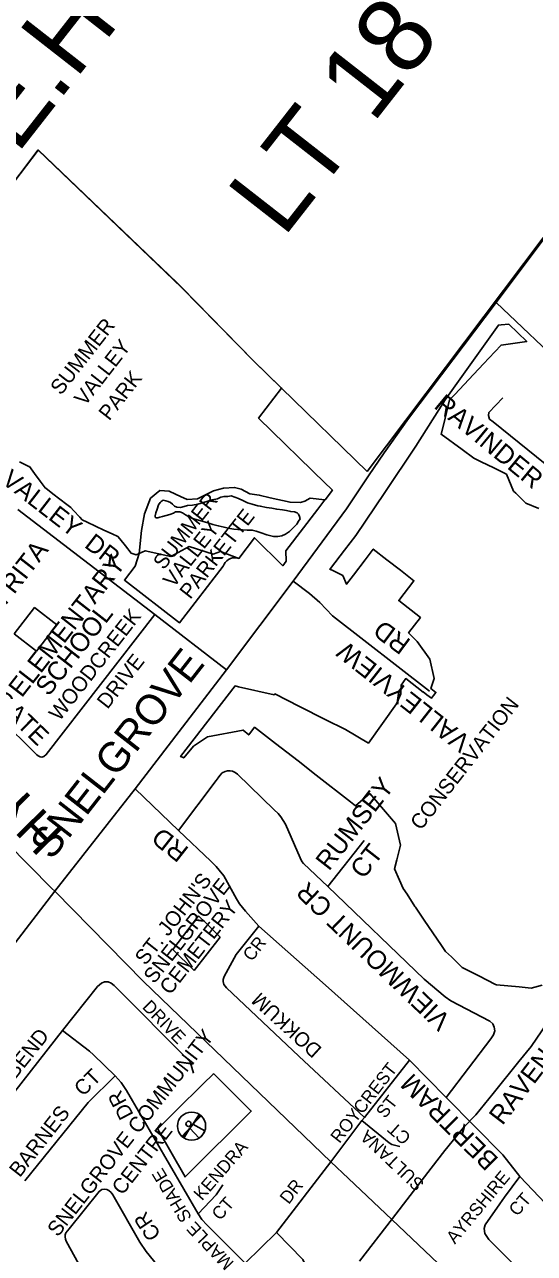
# Model space of a CAD drawing. Extents: x 586326 to 623965, y 4819854 to 4857850.
# Drawn here: x 594587 to 595265, y 4842493 to 4844128 of the extents above; entities that cross this region are included whole.
import ezdxf

# ---------------------------------------------------------------- set-up
doc = ezdxf.new("R2010")
doc.units = 0
for name, color, linetype in [('Cemeteries', 7, 'Continuous'), ('Lots_Concessions', 7, 'Continuous'), ('Major Rds and Hwys', 7, 'Continuous'), ('Major Rds Lbls', 7, 'Continuous'), ('Minor Rd Lbls', 7, 'Continuous'), ('Minor Rds', 7, 'Continuous'), ('Municipal Bdry', 7, 'Continuous'), ('Park Lbls', 7, 'Continuous'), ('Park Outlines', 7, 'Continuous'), ('Proposed Secondary Rds', 7, 'Continuous'), ('Pts of Interest', 7, 'Continuous'), ('Rec Lbls', 7, 'Continuous'), ('Rec Syms', 7, 'Continuous'), ('School Syms_Lbls', 7, 'Continuous'), ('Secondary Rds Lbls', 7, 'Continuous'), ('SWM Ponds', 7, 'Continuous')]:
    doc.layers.add(name, color=color, linetype=linetype)

msp = doc.modelspace()

# ---------------------------------------------------------------- linework, layer by layer
at = {"layer": 'Cemeteries'}
for p, q in [((594818.1, 4842941.8), (594783.8, 4842897.1)), ((594827.7, 4842932.3), (594818.1, 4842941.8)), ((594844.9, 4842915.3), (594827.7, 4842932.3)), ((594812.3, 4842868.8), (594846.8, 4842913.5)), ((594846.8, 4842913.5), (594844.9, 4842915.3)), ((594783.8, 4842897.1), (594812.3, 4842868.8))]:
    msp.add_line(p, q, dxfattribs=at)
at = {"layer": 'Lots_Concessions'}
for p, q in [((595260.4, 4842768), (595323.9, 4842861.7)), ((595244, 4842747.7), (595260.4, 4842768)), ((595210, 4842705.5), (595244, 4842747.7)), ((595186.9, 4842677), (595210, 4842705.5)), ((595170.7, 4842660.7), (595186.9, 4842677)), ((595145.8, 4842629.4), (595170.7, 4842660.7)), ((595127.6, 4842606.1), (595145.8, 4842629.4)), ((595075.9, 4842539.1), (595127.6, 4842606.1)), ((595032.3, 4842482), (595075.9, 4842539.1))]:
    msp.add_line(p, q, dxfattribs=at)
at = {"layer": 'Major Rds and Hwys'}
for points in [[(595213.8, 4843758), (595457.2, 4844082.7)], [(594944.1, 4843386.9), (595015, 4843483.4), (595044.2, 4843527.2), (595064.9, 4843558.1), (595097.4, 4843603.4), (595213.8, 4843758)], [(594626.9, 4842974.4), (594623.1, 4842978.3), (594563.3, 4843039), (594441.7, 4843162.2), (594366, 4843239), (594228, 4843378.9)], [(594855.4, 4843269.1), (594944.1, 4843386.9)], [(594733.6, 4843110.7), (594855.4, 4843269.1)], [(594626.9, 4842974.4), (594733.6, 4843110.7)], [(594341.1, 4842602.5), (594626.9, 4842974.4)], [(594994, 4842614.6), (594744.9, 4842854.2), (594626.9, 4842974.4)], [(595260.2, 4842361.6), (595075, 4842537.6), (595017.6, 4842592.1), (594994, 4842614.6)]]:
    msp.add_lwpolyline(points, dxfattribs=at)
at = {"layer": 'Minor Rds'}
for points in [[(595213.8, 4843758), (595310, 4843666.5), (595318.1, 4843656.8), (595324.3, 4843648.5), (595329.5, 4843640.5), (595334.4, 4843631.5), (595339.1, 4843620.7), (595343.1, 4843609), (595346.2, 4843598.1), (595348.5, 4843586.2), (595355.8, 4843529.1)], [(595355.8, 4843529.1), (595320.1, 4843525.3), (595312.7, 4843525.2), (595304, 4843527.1), (595297.4, 4843529.9), (595290.7, 4843533.8), (595209.7, 4843599.3), (595205.2, 4843602.7), (595203.5, 4843607.5), (595204.2, 4843611.5), (595222.9, 4843631)], [(594759.9, 4843342.7), (594577.9, 4843482.6)], [(594944.1, 4843386.9), (594965.6, 4843370.7), (594979.3, 4843358.9), (594996.3, 4843341.1), (595125.4, 4843240.8)], [(594759.9, 4843342.7), (594615.5, 4843156.3), (594612.4, 4843153.7), (594609.7, 4843152.9), (594607.4, 4843153.2), (594604.9, 4843154.5), (594602.8, 4843156.2)], [(594855.4, 4843269.1), (594759.9, 4843342.7)], [(594602.8, 4843156.2), (594552.4, 4843205.6)], [(594955.6, 4843014.2), (594953.1, 4843018.9), (594933.7, 4843063.6), (594930.7, 4843068.8), (594927.6, 4843073.3), (594923.8, 4843077.8), (594918.8, 4843082.8), (594869.7, 4843130.4), (594866.7, 4843132.5), (594863.2, 4843134.1), (594860.1, 4843134.8), (594856.6, 4843134.7), (594853.4, 4843133.8), (594849.6, 4843131.9), (594846.6, 4843128.6), (594844, 4843125.2), (594841.3, 4843121.7), (594791.4, 4843055.5)], [(594989.9, 4842980.9), (595038.5, 4843042.1)], [(594989.9, 4842980.9), (594957.6, 4843011.5), (594955.6, 4843014.2)], [(595147.4, 4842700.2), (595207, 4842778.1), (595210.4, 4842783.4), (595212.3, 4842788.6), (595211.4, 4842793.4), (595209.4, 4842798.2), (595205.5, 4842801.7), (595153.7, 4842828.5), (595146.1, 4842834.1), (595118.2, 4842857.3), (594989.9, 4842980.9)], [(594898.4, 4842928), (594868.1, 4842890.2), (594852.2, 4842861.1), (594851, 4842857.1), (594850.9, 4842854.2), (594851.9, 4842850.5), (594855.2, 4842846), (594951.3, 4842755), (595038.6, 4842673.4)], [(594637.3, 4842789.2), (594683.7, 4842847.5), (594688.8, 4842852.3), (594693.2, 4842854), (594697.8, 4842853.8), (594701.9, 4842852), (594705.7, 4842848.9), (594806.9, 4842747.6), (594811.2, 4842732.3)], [(594461.5, 4842576.3), (594518, 4842636.8), (594637.3, 4842789.2)], [(594707.4, 4842728.7), (594678.5, 4842756.9), (594672.9, 4842761.6), (594637.3, 4842789.2)], [(595038.6, 4842673.4), (595098.5, 4842749.6)], [(594707.4, 4842728.7), (594671.3, 4842693.5), (594587, 4842589)], [(594817.5, 4842545), (594722.3, 4842709.5), (594715, 4842720.1), (594707.4, 4842728.7)], [(595035.4, 4842669.3), (595038.6, 4842673.4)], [(594994, 4842614.6), (595035.4, 4842669.3)], [(595035.4, 4842669.3), (595071.5, 4842639.8), (595075.3, 4842637.6), (595085.8, 4842634.6)], [(594994, 4842614.6), (594921.8, 4842520.5)], [(595245.3, 4842595), (595225, 4842567.4), (595218.7, 4842558.3)], [(594819.4, 4842418.5), (594795.5, 4842437.6), (594748.4, 4842495), (594740.2, 4842507.3), (594703.9, 4842570.3), (594701.7, 4842573.6), (594698.9, 4842576.1), (594696, 4842577.5), (594692.5, 4842578), (594689.4, 4842577.5), (594685.7, 4842575), (594645.8, 4842525.3), (594641.8, 4842519.7), (594640.9, 4842517.3), (594640.6, 4842514.6), (594641.1, 4842511.4), (594642.1, 4842508.7), (594668.7, 4842460.5), (594672.3, 4842455.4), (594677.9, 4842447.9), (594731.9, 4842383), (594738.7, 4842375.8), (594769.9, 4842350.6)], [(594850.2, 4842584), (594841.5, 4842570.4), (594817.5, 4842545)], [(595218.7, 4842558.3), (595199.1, 4842530.5), (595197.8, 4842525.7), (595198.8, 4842519), (595204, 4842511), (595245.2, 4842469.7)], [(594880.1, 4842479.7), (594829.2, 4842530.5), (594822.5, 4842537.6), (594817.5, 4842545)], [(594921.8, 4842520.5), (594880.1, 4842479.7)], [(595079.2, 4842310.5), (595000.1, 4842386.8), (594987, 4842405.5), (594973.5, 4842446), (594966.1, 4842465.5), (594956.8, 4842484.6), (594921.8, 4842520.5)]]:
    msp.add_lwpolyline(points, dxfattribs=at)
at = {"layer": 'Municipal Bdry'}
for p, q in [((595042.1, 4843533.1), (595458.7, 4844086.3)), ((594190.8, 4843417.7), (594604.8, 4843960.8)), ((594604.8, 4843960.8), (594795.6, 4843778.1)), ((594795.6, 4843778.1), (594891.7, 4843680)), ((594891.7, 4843680), (594928.3, 4843644.1))]:
    msp.add_line(p, q, dxfattribs=at)
msp.add_lwpolyline([(594928.3, 4843644.1), (594928.4, 4843644.1), (595042.1, 4843533.1)], dxfattribs=at)
at = {"layer": 'Park Outlines'}
for points in [[(594580.1, 4843546), (594592.3, 4843539.9), (594593.1, 4843539.5), (594599.9, 4843530.3), (594607.3, 4843520.4), (594614.1, 4843511.3), (594614.8, 4843510.7), (594624.3, 4843503.5), (594633.7, 4843496.2), (594643.1, 4843489), (594648.2, 4843485.1), (594652, 4843481), (594660.1, 4843472.1), (594663.4, 4843468.6), (594670, 4843465.5), (594681.1, 4843460.3), (594692.1, 4843455.2), (594703.1, 4843450), (594710.9, 4843446.4), (594713.2, 4843443.6), (594720.8, 4843434), (594728.4, 4843424.4), (594735.3, 4843422), (594738.9, 4843423.8), (594742.2, 4843454.5), (594746.2, 4843476.6), (594754.4, 4843497.4), (594766.6, 4843507.9), (594779, 4843506.8), (594787.3, 4843502.9), (594794.1, 4843499.7), (594803.1, 4843495.9), (594816.8, 4843496.5), (594837.9, 4843507.3), (594851.3, 4843510.8), (594866.1, 4843511.8), (594874.9, 4843509.6), (594886.5, 4843503.2), (594898.7, 4843501.7), (594913.3, 4843498.2), (594939.8, 4843492.2), (594953.6, 4843492), (594959.4, 4843493.4), (594966.7, 4843497.7), (594986.2, 4843495.4), (594986.3, 4843495.5), (594996.1, 4843508.3), (594995.5, 4843508.9), (594994, 4843510.3), (594986.9, 4843517.3), (594897.9, 4843604.2), (594928.4, 4843644.1), (594907.1, 4843665), (594891.8, 4843680.1), (594795.6, 4843778.2), (594789.5, 4843784.1), (594604.8, 4843961), (594529.7, 4843862.3)], [(595270.6, 4843484), (595253.3, 4843491.1), (595239.9, 4843504.1), (595236.8, 4843507.1), (595227.5, 4843529.5), (595210.6, 4843537.8), (595193.8, 4843546), (595184.1, 4843550.7), (595168.5, 4843562.2), (595140.7, 4843582.6), (595144.1, 4843596.7), (595151.9, 4843628.3), (595158.7, 4843635.6), (595177.4, 4843655.4), (595197.2, 4843676.5), (595212.3, 4843692.5), (595220.5, 4843701.3), (595254.5, 4843706), (595230.7, 4843729), (595220.7, 4843728.2), (595216.8, 4843727.9), (595146.2, 4843628.3), (595106.9, 4843566.6), (595065.6, 4843504.9), (595027.4, 4843448.1), (595012.3, 4843428.5), (594993.5, 4843404), (594992.6, 4843403.1), (594997.4, 4843400.8), (595009.8, 4843394.8), (595014.7, 4843383.1), (595024, 4843395.3), (595039.5, 4843415.5), (595050.5, 4843429.8), (595068.5, 4843415.7), (595086.5, 4843401.6), (595104.5, 4843387.6), (595084.3, 4843361.3), (595113.1, 4843338.7), (595097.3, 4843318.3), (595109, 4843306.7), (595125.8, 4843283.4), (595131.3, 4843257.6), (595130.4, 4843254.8), (595126.9, 4843244.4), (595133.7, 4843239.1), (595130.7, 4843235.1), (595127.7, 4843231.3), (595121.7, 4843235.9), (595116.9, 4843239.7), (595116.7, 4843239.5), (595093.7, 4843257.4), (595087.5, 4843248.5), (595087.3, 4843237.3), (595081.5, 4843223.9), (595043.9, 4843171.7), (595013.6, 4843189.5), (594986.4, 4843203.2), (594952.4, 4843220.4), (594919.6, 4843237), (594918.6, 4843235.8), (594871.2, 4843246.7), (594866.6, 4843247.8), (594794.2, 4843153.7), (594796.6, 4843152.7), (594798.5, 4843152), (594811.4, 4843167.7), (594830.2, 4843179.8), (594877.4, 4843189), (594884.8, 4843182.6), (594892.7, 4843192.8), (594920.5, 4843171.2), (594950.6, 4843147.8), (594974.6, 4843129), (595020.3, 4843093.4), (595027, 4843088), (595045.8, 4843104.4), (595074.6, 4843070.8), (595079.8, 4843064.7), (595086.7, 4843036), (595081.7, 4843016.1), (595078.8, 4843004.5), (595085.5, 4842989.4), (595090.4, 4842978.3), (595095.4, 4842970.6), (595105.7, 4842954.2), (595106.5, 4842953.1), (595118.1, 4842936.2), (595129.7, 4842919.2), (595141.3, 4842902.3), (595146.6, 4842894.5), (595154.3, 4842887), (595168.8, 4842872.8), (595191, 4842861.7), (595213.1, 4842850.5), (595214.4, 4842849.9), (595244.3, 4842847.2), (595260.4, 4842845.7), (595274.9, 4842849.4)]]:
    msp.add_lwpolyline(points, dxfattribs=at)
for points in [[(594738.9, 4843423.8), (594747.1, 4843427.6), (594781, 4843420), (594805.6, 4843433.1), (594837.7, 4843423), (594847.3, 4843426.4), (594871.8, 4843417.4), (594892.4, 4843444.9), (594930, 4843407.7), (594934.4, 4843413.6), (594934, 4843427.7), (594976.7, 4843483.1), (594986.2, 4843495.4), (594966.7, 4843497.7), (594959.4, 4843493.4), (594953.6, 4843492), (594939.8, 4843492.2), (594913.3, 4843498.2), (594898.7, 4843501.7), (594886.5, 4843503.2), (594874.9, 4843509.6), (594866.1, 4843511.8), (594851.3, 4843510.8), (594837.9, 4843507.3), (594816.8, 4843496.5), (594803.1, 4843495.9), (594794.1, 4843499.7), (594787.3, 4843502.9), (594779, 4843506.8), (594766.6, 4843507.9), (594754.4, 4843497.4), (594746.2, 4843476.6), (594742.2, 4843454.5)], [(594805.6, 4843433.1), (594781, 4843420), (594747.1, 4843427.6), (594738.9, 4843423.8), (594733.9, 4843407.1), (594719.5, 4843388.5), (594792.8, 4843331.8), (594850.9, 4843406.9), (594852, 4843409.6), (594853.6, 4843412), (594855.6, 4843414.1), (594857.9, 4843415.9), (594860.5, 4843417.2), (594863.2, 4843418), (594866.1, 4843418.3), (594869, 4843418.1), (594871.8, 4843417.4), (594847.3, 4843426.4), (594837.7, 4843423)], [(594838, 4842731.9), (594837.8, 4842731.7), (594823.9, 4842717.9), (594788.9, 4842683.1), (594763.6, 4842657.9), (594763.7, 4842657.8), (594763.8, 4842657.7), (594800.1, 4842594.4), (594810, 4842604.2), (594818.5, 4842612.7), (594827.7, 4842621.8), (594840.1, 4842634.2), (594851.5, 4842645.4), (594888, 4842681.7), (594888.2, 4842681.9)]]:
    msp.add_lwpolyline(points, close=True, dxfattribs=at)
at = {"layer": 'Proposed Secondary Rds'}
for points in [[(594791.4, 4843055.5), (594733.6, 4843110.7)], [(594845.6, 4843002.6), (594841.3, 4843007.5), (594834.5, 4843014.3), (594791.4, 4843055.5)], [(594898.4, 4842928), (594880.5, 4842947.8), (594872.7, 4842957.9), (594868.4, 4842964.4), (594851.6, 4842995.2), (594845.6, 4843002.6)], [(595098.5, 4842749.6), (594987.1, 4842849.3), (594898.4, 4842928)], [(595147.4, 4842700.2), (595098.5, 4842749.6)], [(595245.3, 4842595), (595222.6, 4842623.5), (595147.4, 4842700.2)], [(595279.5, 4842559), (595245.3, 4842595)]]:
    msp.add_lwpolyline(points, dxfattribs=at)
at = {"layer": 'Rec Syms'}
for p, q in [((594820.3, 4842676.6), (594797.2, 4842647.1)), ((594797.2, 4842647.1), (594806.5, 4842659))]:
    msp.add_line(p, q, dxfattribs=at)
msp.add_lwpolyline([(594808.7, 4842661.9), (594795.9, 4842648.2), (594797.2, 4842647.1), (594798.6, 4842646.1), (594806.5, 4842659), (594818.8, 4842646), (594819.5, 4842646.5), (594820.4, 4842647.2), (594820.9, 4842647.6), (594821, 4842647.7), (594821.3, 4842648), (594822.2, 4842648.7), (594822.8, 4842649.5), (594823.5, 4842650.3), (594824.1, 4842651), (594824.6, 4842651.8), (594824.9, 4842652.2), (594825.2, 4842652.8), (594825.6, 4842653.6), (594825.8, 4842654.1), (594826.5, 4842655.7), (594810.7, 4842664.5), (594821.7, 4842675.5), (594820.3, 4842676.6), (594819.1, 4842677.5)], close=True, dxfattribs=at)
for centre, radius in [((594808.8, 4842661.9), 18.7), ((594804.8, 4842664.9), 3.5)]:
    msp.add_circle(centre, radius, dxfattribs=at)
at = {"layer": 'School Syms_Lbls'}
msp.add_lwpolyline([(594572.8, 4843317.1), (594600.1, 4843352), (594629.7, 4843328.9), (594602.4, 4843294)], close=True, dxfattribs=at)
at = {"layer": 'SWM Ponds'}
msp.add_lwpolyline([(594766.6, 4843472.4), (594770.3, 4843473.1), (594774.9, 4843474.4), (594779.9, 4843475.9), (594784.9, 4843477.6), (594787.4, 4843479.5), (594790.3, 4843479.5), (594793.2, 4843479.4), (594796.7, 4843478.2), (594800.6, 4843475.4), (594804.7, 4843473.2), (594809.3, 4843471.1), (594813.3, 4843469.6), (594817.8, 4843468.5), (594824.2, 4843466.6), (594830.5, 4843464.6), (594837.2, 4843462.5), (594844.3, 4843460.8), (594852, 4843458.8), (594859.9, 4843457.2), (594865, 4843456.5), (594870.2, 4843455.8), (594876.6, 4843455.3), (594882.8, 4843454.9), (594889.6, 4843455), (594894.8, 4843453.6), (594901.2, 4843451.5), (594909, 4843448.8), (594917.9, 4843446.5), (594923.6, 4843446.6), (594929, 4843447.3), (594933.9, 4843449.8), (594939.1, 4843453.3), (594943.8, 4843457.9), (594948.6, 4843462.9), (594950.8, 4843467.1), (594953, 4843470), (594952.4, 4843473.2), (594950.9, 4843476.1), (594949.4, 4843478.2), (594945.5, 4843479.2), (594940.8, 4843479.8), (594935.1, 4843481.1), (594929.6, 4843482.2), (594922.1, 4843482.9), (594915.7, 4843484.1), (594908.3, 4843485.2), (594900.2, 4843487), (594896.7, 4843487.3), (594889.2, 4843489.6), (594883.3, 4843491.5), (594877.9, 4843494), (594871.3, 4843497.1), (594866.2, 4843499.1), (594861.6, 4843500.7), (594857.2, 4843500), (594852, 4843499.9), (594847.5, 4843498.7), (594843.1, 4843496.5), (594836.3, 4843495.3), (594828.9, 4843493), (594821.5, 4843490.7), (594817.1, 4843489.7), (594810, 4843488.3), (594803.3, 4843487.7), (594798.9, 4843486.6), (594794, 4843485.3), (594789, 4843485.8), (594786.2, 4843486.9), (594783.6, 4843489.6), (594780.6, 4843491.7), (594777.8, 4843493.3), (594774.7, 4843494.1), (594771.1, 4843494.7), (594768.4, 4843493.2), (594766.9, 4843491.7), (594764.9, 4843488.5), (594763.1, 4843482.8), (594761.4, 4843478), (594760.3, 4843474), (594760.6, 4843472.4), (594761.5, 4843471.2), (594764, 4843471.3)], close=True, dxfattribs=at)

# ---------------------------------------------------------------- texts
at = {"layer": 'Cemeteries'}
for s, p in [("ST. JOHN'S", (594747.5, 4842874.7)), ('SNELGROVE', (594759.1, 4842850.3)), ('CEMETERY', (594780.3, 4842835.4))]:
    msp.add_text(s, height=20, rotation=52, dxfattribs=at).set_placement(p)
at = {"layer": 'Lots_Concessions'}
for s, p in [('CN 1 E.H.S.', (594366.2, 4843684.9)), ('LT 18', (594931, 4843842.9))]:
    msp.add_text(s, height=100, rotation=52, dxfattribs=at).set_placement(p)
at = {"layer": 'Major Rds Lbls'}
msp.add_text(' HY  10', height=50, rotation=134.6024, dxfattribs=at).set_placement((594654.6, 4843040.7))
at = {"layer": 'Minor Rd Lbls'}
for s, height, rotation, p in [('RAVINDER', 25, 320.4576, (595129.8, 4843618.5)), ('  VALLEY  DR', 24, 322.2747, (594540.8, 4843529.3)), ('WOODCREEK', 20, 52, (594633.1, 4843199.8)), ('RD', 25, 143.4388, (595101.7, 4843308)), ('VALLEYVIEW', 25, 141.8071, (595181.6, 4843177.3)), ('OLDGATE', 24, 315.812, (594494.6, 4843273.4)), ('DRIVE', 20, 52, (594697, 4843215.8)), ('RUMSEY', 25, 52, (594991.5, 4843000.5)), ('CT', 25, 52, (595037.5, 4842989.5)), ('VIEWMOUNT CR', 25.002, 136.2275, (595154.9, 4842805)), ('CR', 17, 51.9031, (594888.9, 4842880.1)), ('RAVENSCROFT', 25.002, 52.5236, (595222.2, 4842661.9)), ('DOKKUM', 19.2, 137.6539, (594983.3, 4842765.3)), ('DRIVE', 17, 314.0628, (594742.2, 4842819.7)), ('SOUTHBEND', 20, 51.4636, (594516, 4842650.4)), ('CT', 20, 44.2984, (594664.4, 4842700.5)), ('ROYCREST', 17, 52, (595005.5, 4842638)), ('DR', 20, 117.8166, (594732.1, 4842677.2)), ('ST', 17, 52, (595066.1, 4842671.1)), ('BARNES', 20, 51.9692, (594580.3, 4842592.6)), ('SULTANA', 17, 136.6488, (595119.5, 4842586.2)), ('CT', 17, 138.3817, (595101.9, 4842648.3)), ('KENDRA', 17, 48.9838, (594822.7, 4842561.8)), ('SHADE', 17, 120.8179, (594809.8, 4842540.2)), ('AYRSHIRE', 17, 50.2137, (595159, 4842504.1)), ('DR', 17, 52, (594938, 4842556.9)), ('CT', 17, 49.2053, (595241.9, 4842540.9)), ('CT', 17, 48.6032, (594846.7, 4842535.3)), ('CR', 20, 123.578, (594768.8, 4842517.7)), ('MAPLE', 17, 133.5938, (594866.2, 4842480.4))]:
    msp.add_text(s, height=height, rotation=rotation, dxfattribs=at).set_placement(p)
at = {"layer": 'Park Lbls'}
for s, height, p in [('SUMMER', 19.99, (594635, 4843633.5)), ('VALLEY', 19.99, (594666.9, 4843619)), ('PARK', 19.99, (594699.3, 4843599.6)), ('SUMMER', 19.99, (594771.8, 4843401.1)), ('PARKETTE', 19.99, (594807, 4843362)), ('VALLEY', 19.99, (594784.9, 4843377.2)), ('CONSERVATION', 19.992, (595113.7, 4843054.4))]:
    msp.add_text(s, height=height, rotation=52, dxfattribs=at).set_placement(p)
at = {"layer": 'Pts of Interest'}
msp.add_text('SNELGROVE', height=39.98, rotation=52, dxfattribs=at).set_placement((594622.7, 4843014.6))
at = {"layer": 'Rec Lbls'}
for s, p in [('SNELGROVE COMMUNITY ', (594631, 4842513.4)), ('             CENTRE', (594657.3, 4842492.8))]:
    msp.add_text(s, height=20, rotation=52, dxfattribs=at).set_placement(p)
at = {"layer": 'School Syms_Lbls'}
for s, p in [('St. RITA', (594541.8, 4843329)), ('ELEMENTARY', (594582.9, 4843231)), ('SCHOOL', (594618.8, 4843232.7))]:
    msp.add_text(s, height=25, rotation=52, dxfattribs=at).set_placement(p)
at = {"layer": 'Secondary Rds Lbls'}
for s, rotation, p in [('RD', 141.8613, (594806.6, 4843031.1)), ('BERTRAM', 135.1463, (595218.4, 4842618.3))]:
    msp.add_text(s, height=25, rotation=rotation, dxfattribs=at).set_placement(p)

doc.saveas('drawing.dxf')
